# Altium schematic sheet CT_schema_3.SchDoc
size 284 x 243 mm
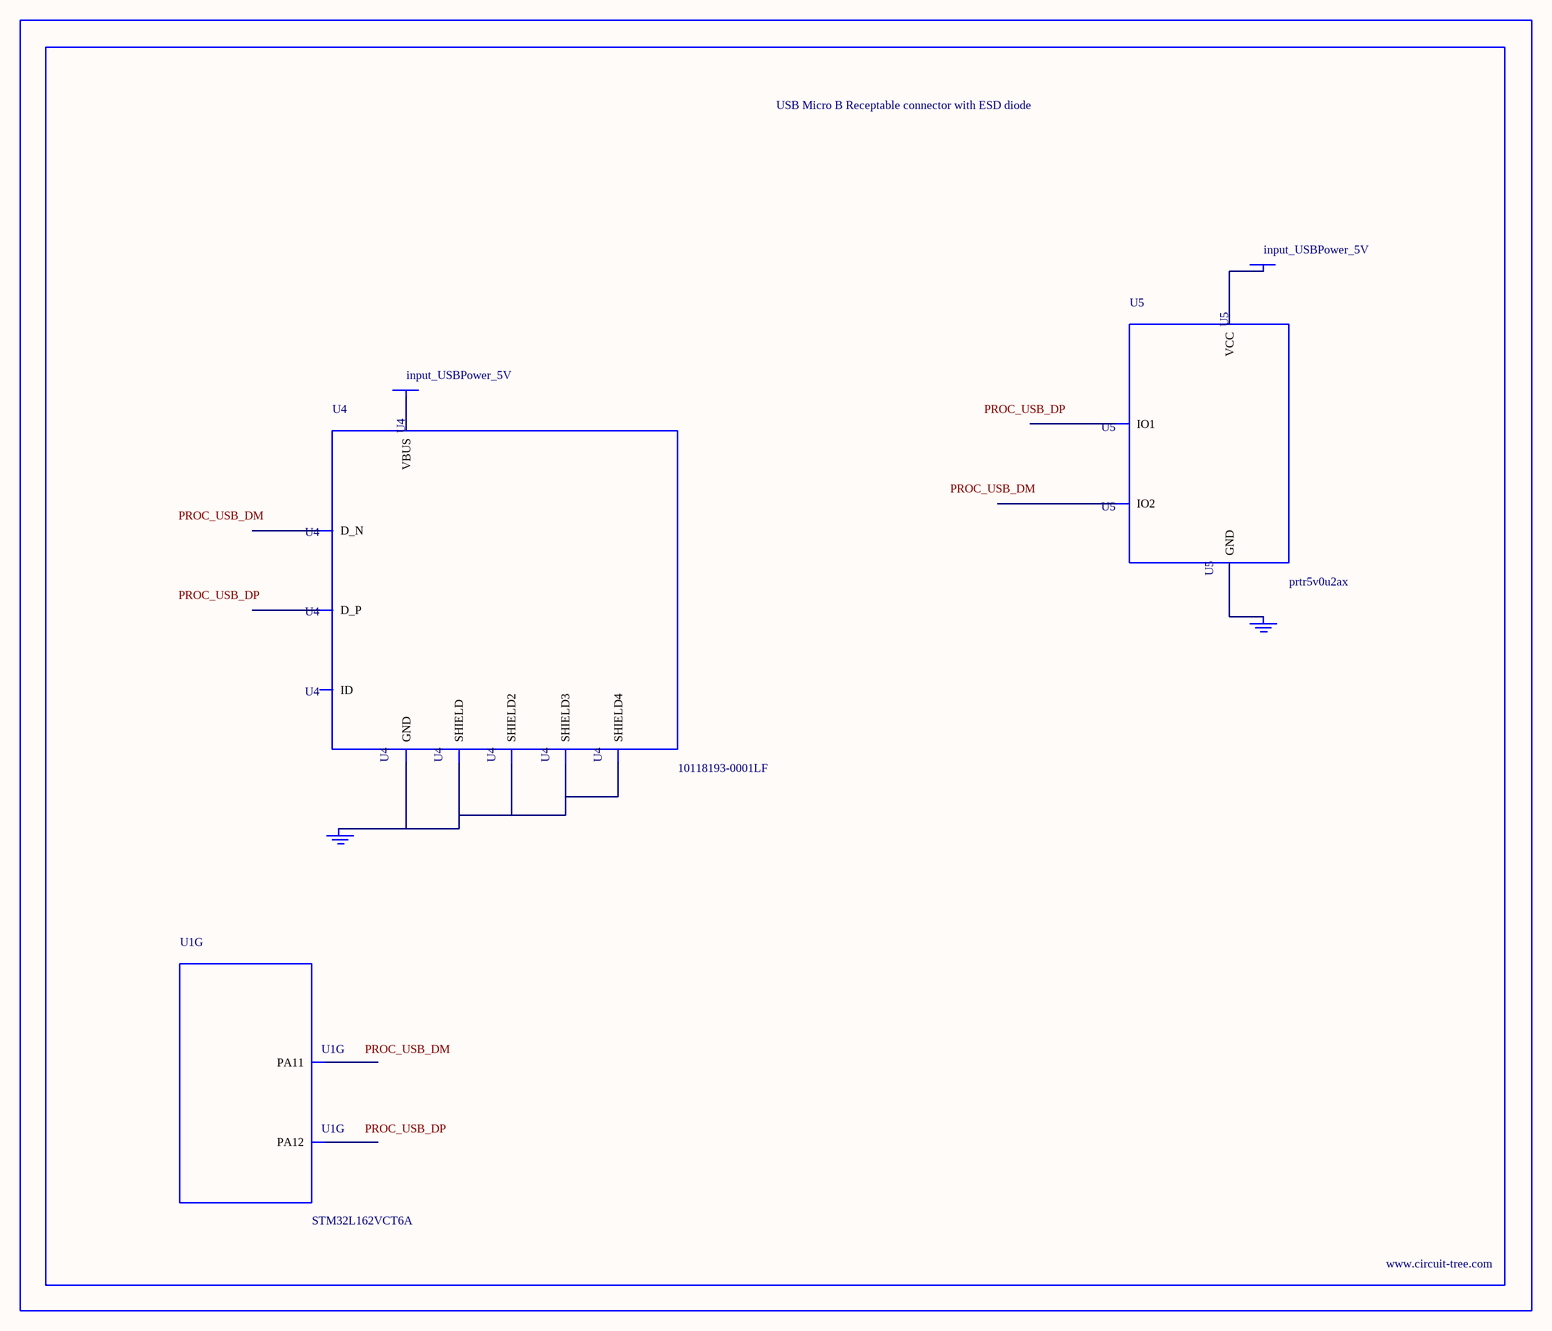
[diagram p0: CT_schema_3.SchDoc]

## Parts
BORDER2  (no value)
GND_INSTANCE_2_0  (no value)
GND_INSTANCE_2_1  (no value)
POWER_INSTANCE_2_0  input_USBPower_5V
POWER_INSTANCE_2_1  input_USBPower_5V
U1  STM32L162VCT6A  [LQFP100]  (part G of 9)
U4  10118193-0001LF  [FCI_10118193-0001LF]
U5  prtr5v0u2ax  [SOT143B]

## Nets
NetGND_INSTANCE_2_0_0: GND_INSTANCE_2_0.0(GND) U4.5(GND) U4.6(SHIELD) U4.7(SHIELD2) U4.8(SHIELD3) U4.9(SHIELD4)
NetGND_INSTANCE_2_1_0: GND_INSTANCE_2_1.0(GND) U5.1(GND)
NetPOWER_INSTANCE_2_0_0: POWER_INSTANCE_2_0.0(PWR) U4.1(VBUS)
NetPOWER_INSTANCE_2_1_0: POWER_INSTANCE_2_1.0(PWR) U5.4(VCC)

Not connected (* = marked no-connect by the designer): U1 70(PA11) 71(PA12); U4 2(D_N) 3(D_P) 4(ID); U5 2(IO1) 3(IO2)

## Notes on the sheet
- Labels drawn without touching a wire or pin: PROC_USB_DM, PROC_USB_DP

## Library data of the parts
BORDER2 = BORDER_PAGE2
GND_INSTANCE_2_0 GND_INSTANCE_2_1 = GND
POWER_INSTANCE_2_0 POWER_INSTANCE_2_1 = PWR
